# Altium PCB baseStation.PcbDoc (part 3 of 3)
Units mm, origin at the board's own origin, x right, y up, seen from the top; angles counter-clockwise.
Board outline 130 x 90 mm, 4 copper layers (Top Layer, Ground Layer, Power Layer, Bottom Layer), stack 1.574 mm thick; 252 components, 154 nets, 772 pads, 1223 vias.
Unrouted connection lines stored in the file: 134.
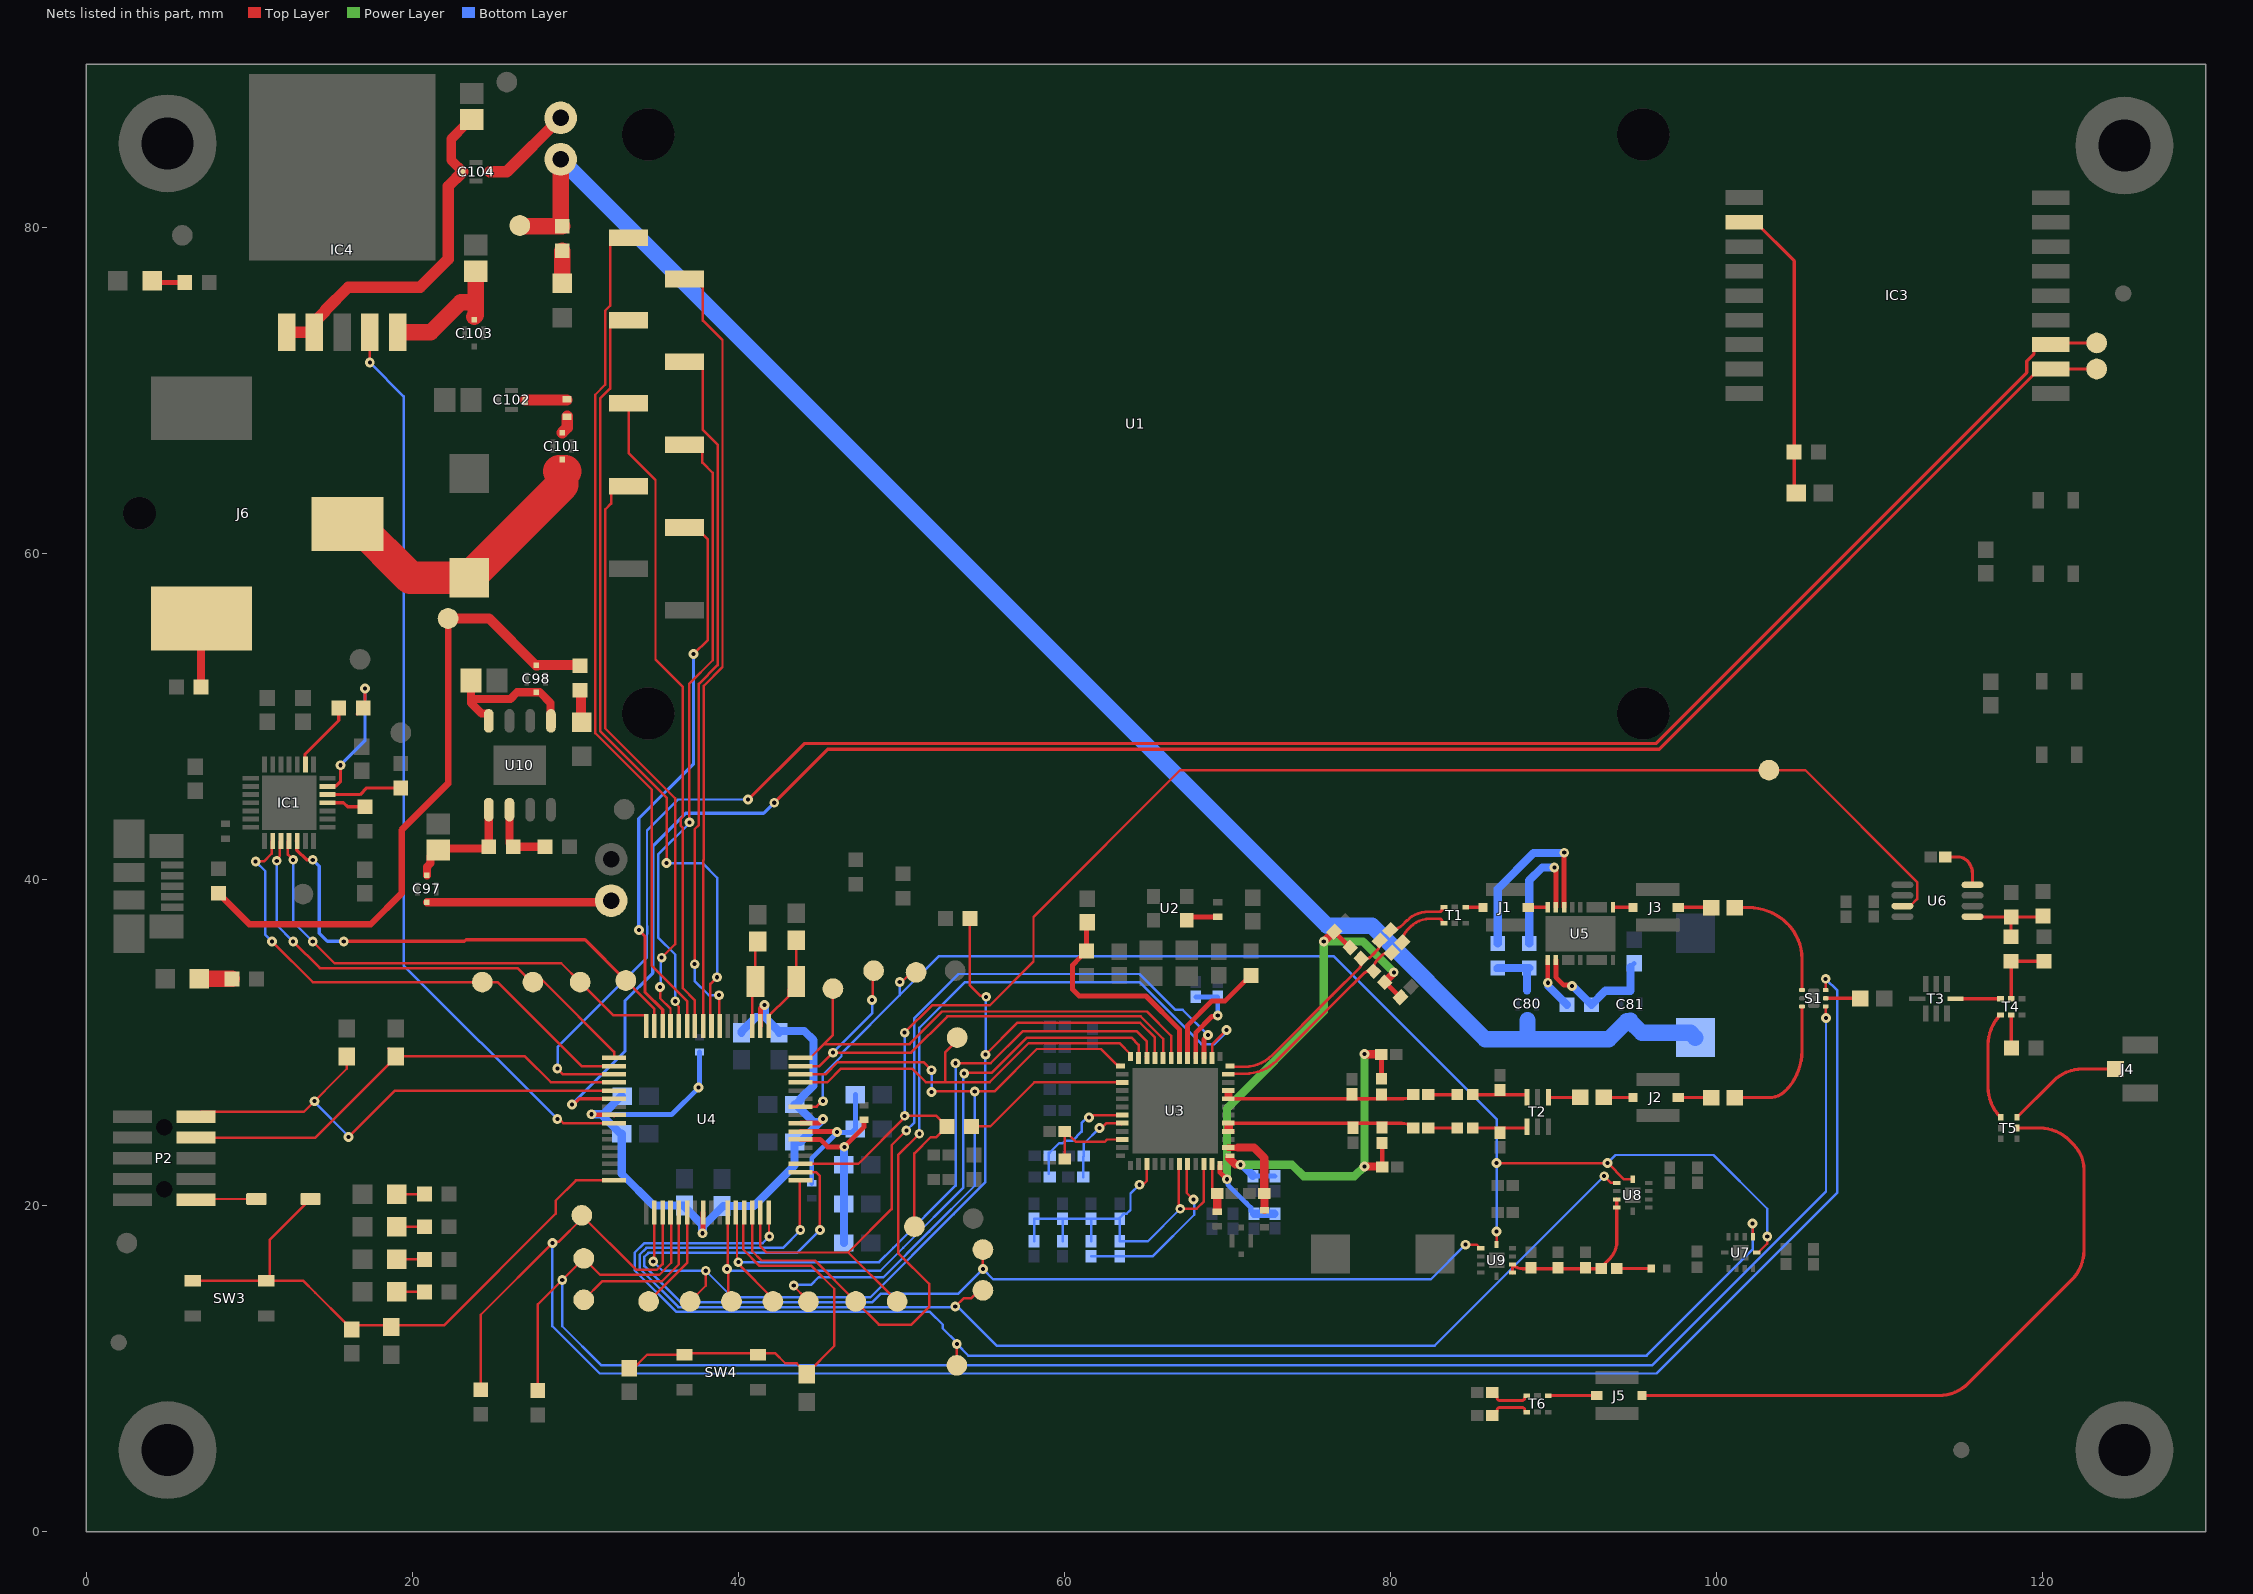
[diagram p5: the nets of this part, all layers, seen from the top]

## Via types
v1: diameter 0.6, hole 0.25, Top Layer to Bottom Layer, tented both sides, 1129 vias
v2: diameter 0.6, hole 0.25, Top Layer to Bottom Layer, 71 vias
v3: diameter 0.66, hole 0.33, Top Layer to Bottom Layer, 17 vias
v4: diameter 0.5, hole 0.2, Top Layer to Bottom Layer, 6 vias

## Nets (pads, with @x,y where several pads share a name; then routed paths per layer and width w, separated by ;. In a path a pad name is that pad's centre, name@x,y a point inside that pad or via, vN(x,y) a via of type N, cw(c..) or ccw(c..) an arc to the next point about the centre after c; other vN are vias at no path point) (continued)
NetC30_2: C30.2 L4.1 | length 1.8
  Top Layer w0.199: C30.2@82.306,26.8 L4.1@84.09,26.8
NetC32_2: C32.2 L4.2 T2.3 | length 3.5
  Top Layer w0.199: L4.2@85.047,26.8 86.71,26.8 88.319,26.8 88.37,26.749 T2.3@88.37,26.64
NetC39_1: C39.1 T2.1 | length 2
  Top Layer w0.199: T2.1@89.68,26.64 ccw(c89.704,26.664) 89.704,26.63 C39.1@91.624,26.63
  Top Layer w0.62: C39.1@91.619,26.635 C39.1@91.624,26.63
NetC39_2: C39.2 J2.IN | length 1.8
  Top Layer w0.199: C39.2@93.076,26.63 J2.IN@94.865,26.63
NetC41_2: C41.2 L6.1 | length 1.8
  Top Layer w0.199: C41.2@82.306,24.76 L6.1@84.09,24.76
NetC51_2: C51.2 L6.2 T2.4 | length 3.4
  Top Layer w0.199: L6.2@85.047,24.76 86.71,24.76 88.319,24.76 88.37,24.81 T2.4@88.37,24.84
NetC59_2: C59.2 C60.2 U3.8 | length 10.7
  Top Layer w0.15: U3.8@67.55,22.55 67.5,22.5 67.5,20.78 v1(67.919,20.361)
  Bottom Layer w0.15: C59.2@61.64,16.894 C60.2@63.39,16.894 65.419,16.894 67.96,19.435 67.96,20.32 v1(67.919,20.361)
NetC62_2: C62.2 C63.2 C64.2 C65.2 C66.2 C67.2 C68.2 C69.2 FB5.2 U4.8 U4.24 U4.34 U4.56 | length 52.5
  Top Layer w0.3: v1(31,25.6) 31.036,25.564 32.375,25.564 U4.56@32.385,25.554 ; v1(37.8,18.3) 37.836,18.336 U4.8@37.836,19.575 ; U4.34@41.351,31.015 41.351,32.086 41.565,32.3 v1(41.6,32.3) ; U4.24@43.825,25.056 44.956,25.056 v1(45.2,25.3)
  Power Layer w0.5: v1(31,25.6) v1@31.019,25.581
  Bottom Layer w0.3: 31.593,25.581 35.912,25.581 v1(37.565,27.234) 37.63,27.298 FB5.2@37.63,29.416
  Bottom Layer w0.5: C62.2@32.874,26.7 32.8,26.7 31.719,25.619 31.019,25.619 v1(31,25.6) 31.019,25.581 31.593,25.581 32.774,24.4 C63.2@32.848,24.4 32.848,21.952 34.8,20 C66.2@36.7,20 36.7,19.926 37.781,18.845 37.781,18.319 v1(37.8,18.3) 37.819,18.319 37.819,18.719 39.074,19.974 40.964,19.974 43.452,22.462 C68.2@43.452,23.9 43.8,23.9 v1@45.019,25.119 ; C64.2@40.2,30.6 40.2,30.674 41.081,31.555 41.619,31.555 ; v1(41.6,32.3) 41.619,32.281 41.619,31.625 41.619,31.555 ; C69.2@43.452,26.2 C69.2@43.526,26.2 ; v1(45.2,25.3) v1@45.019,25.119 ; 41.619,31.555 42.5,30.674 C65.2@42.5,30.6 42.6,30.7 44.04,30.7 44.6,30.14 44.6,27.348 43.805,26.553 43.805,26.479 C69.2@43.526,26.2 ; C69.2@43.526,26.2 44.607,25.119 v1@45.019,25.119
NetC70_2: C70.2 C71.2 FB6.2 U4.23 | length 9.4
  Top Layer w0.3: U4.23@43.815,24.538 46.009,24.538 v1(46.047,24.501)
  Bottom Layer w0.3: FB6.2@44.5,21.354 44.5,22.9 46.047,24.447 v1(46.047,24.501) ; v1@46.024,24.476 46.95,24.476 C70.2@47.174,24.7 C71.2@47.174,26.8
NetC72_2: C72.2 IC3.2 R12.1 | length 18.3
  Top Layer w0.2: IC3.2@101.686,80.3 102.379,80.3 104.749,77.93 R12.1@104.749,66.2 104.749,63.825 C72.2@104.874,63.7
NetC73_2: C73.2 C74.2 C75.2 FB7.1 U4.22 | length 10.9
  Top Layer w0.3: U4.22@43.815,24.055 45.023,24.055 45.478,23.6 v2(46.5,23.6) 47.7,24.8 FB7.1@47.7,25.246
  Bottom Layer w0.5: C73.2@46.474,17.7 C74.2@46.474,20.1 C75.2@46.474,22.5 46.474,23.574 v2(46.5,23.6)
NetC80_3: C80.3 R24.2 R25.2 | length 3.5
  Bottom Layer w0.3: R25.2@86.46,34.459 R25.2@86.57,34.569 R25.2@86.571,34.568 ; R24.2@88.37,34.438 R24.2@88.5,34.568
  Bottom Layer w0.5: R25.2@86.571,34.568 R24.2@88.5,34.568 ; C80.3@88.37,33.185 R24.2@88.37,34.438
NetC81_3: C81.3 C83.2 R23.2 U5.2 | length 8.5
  Top Layer w0.3: U5.2@90.14,35.05 90.14,34 90.623,33.517 91.063,33.517 v1(91.12,33.46)
  Bottom Layer w0.3: v1(91.12,33.46) v1@91.172,33.46 ; C83.2@94.71,34.624 C83.2@94.94,34.854
  Bottom Layer w0.5: v1@91.172,33.46 92.321,32.311 93.185,33.175 C81.3@94.71,33.175 C83.2@94.71,34.624
NetC84_1: C84.1 J2.OUT | length 2
  Top Layer w0.199: J2.OUT@97.64,26.63 ccw(c97.664,26.654) 97.664,26.62 C84.1@99.664,26.62
  Top Layer w0.62: C84.1@99.659,26.625 C84.1@99.664,26.62
NetC84_2: C84.2 S1.6 | length 8.7
  Top Layer w0.199: C84.2@101.116,26.62 102.118,26.62 103.229,26.62 ccw(c103.229,28.01) 104.211,27.026 ccw(c101.753,29.486) 105.23,29.486 S1.6@105.23,32.21
NetC85_1: C85.1 S1.2 | length 2.1
  Top Layer w0.199: S1.2@106.68,32.71 108.79,32.71 cw(c108.79,32.676) C85.1@108.814,32.7
NetC86_1: C86.1 J3.OUT | length 2.1
  Top Layer w0.199: J3.OUT@97.635,38.29 99.616,38.29 cw(c99.616,38.222) 99.651,38.28 cw(c99.616,38.222) C86.1@99.664,38.27
  Top Layer w0.62: C86.1@99.64,38.28 cw(c99.64,38.246) C86.1@99.664,38.27 99.654,38.28 99.651,38.28 C86.1@99.64,38.28
NetC86_2: C86.2 S1.4 | length 7.8
  Top Layer w0.199: C86.2@101.116,38.27 101.968,38.27 cw(c101.968,34.925) 104.332,37.292 cw(c102.168,35.125) 105.23,35.125 105.23,35.124 S1.4@105.23,33.21
NetC89_2: C89.2 U6.4 | length 3
  Top Layer w0.199: C89.2@114.026,41.38 114.781,41.38 cw(c114.781,40.561) 115.36,41.14 cw(c114.563,40.343) 115.69,40.343 U6.4@115.69,39.665
NetC90_1: C90.1 R31.1 | length 2.1
  Top Layer w0.199: R31.1@93.879,16.13 cw(c93.903,16.106) 93.903,16.14 C90.1@95.975,16.14
  Top Layer w0.3: C90.1@95.97,16.13 ccw(c95.97,16.164) C90.1@95.994,16.14
NetC97_1: C97.1 C100.2 R35.2 U10.1 | length 7.4
  Top Layer w0.5: C97.1@20.9,40.247 20.9,40.772 21.122,40.994 21.122,41.397 21.524,41.799 C100.2@21.6,41.799 ; C100.2@21.55,41.799 21.65,41.9 24.597,41.9 R35.2@24.698,42 24.696,42.001 24.696,44.274 U10.1@24.695,44.275
NetC97_3: C97.3 W1.1 | length 11.3
  Top Layer w0.5: C97.3@20.9,38.597 32.097,38.597 W1.1@32.2,38.7
NetC98_3: C98.3 C99.2 U10.5 U10.8 | length 9.6
  Top Layer w0.5: C99.2@23.598,52.2 23.598,51.072 ; U10.8@24.695,49.725 24.695,50.123 24.649,50.169 24.251,50.169 23.598,50.822 23.598,51.072 ; U10.5@28.505,49.725 28.486,49.744 28.486,50.814 27.825,51.475 C98.3@27.6,51.475 26.421,51.475 26.018,51.072 23.598,51.072
NetC101_1: C101.1 C105.1 J6.1 | length 18.3
  Top Layer w2: J6.1@16.025,61.8 16.575,61.8 19.875,58.5 C105.1@23.5,58.5 29.2,64.2 29.2,65.025 29.376,65.025 29.382,65.031 29.018,65.031
NetC101_3: C101.3 FB8.1 | length 1.1
  Top Layer w0.7: C101.3@29.2,67.4 29.5,67.7 FB8.1@29.5,68.396
NetC102_1: C102.1 FB8.2 | length 2.5
  Top Layer w0.7: C102.1@26.925,69.4 FB8.2@29.467,69.4
NetC103_3: C103.3 C107.2 IC4.5 | length 8.4
  Top Layer w1: IC4.5@19.104,73.558 21.137,73.558 22.979,75.4 23.9,75.4 ; 23.8,74.5 23.9,74.6 23.9,75.4 ; C107.2@23.9,77.3 23.9,75.4
NetC104_1: C104.1 C108.2 IC4.1 IC4.2 | length 21.4
  Top Layer w0.6: C104.1@23.1,83.4 22.4,84.1 22.4,85.422 C108.2@23.275,86.297
  Top Layer w0.7: IC4.1@12.296,73.558 IC4.2@13.998,73.558 13.998,74.167 14.666,74.836 14.666,74.908 16.085,76.327 20.497,76.327 22.2,78.03 22.2,82.5 C104.1@23.1,83.4
NetC104_3: C104.3 W2.1 | length 5.7
  Top Layer w0.7: C104.3@24.75,83.4 25.8,83.4 W2.1@29.1,86.7
NetD1_A: D1.A R15.1 | length 1.7
  Top Layer w0.15: D1.A@19.05,20.7 R15.1@20.749,20.7
NetD2_A: D2.A R16.1 | length 1.7
  Top Layer w0.15: D2.A@19.05,18.7 R16.1@20.749,18.7
NetD3_A: D3.A R17.1 | length 1.7
  Top Layer w0.15: D3.A@19.05,16.7 R17.1@20.749,16.7
NetD4_A: D4.A R18.1 | length 1.7
  Top Layer w0.15: D4.A@19.05,14.7 R18.1@20.749,14.7
NetD5_K: D5.K P2.10 | length 3.7
  Top Layer w0.15: P2.10@6.79,20.4 D5.K@10.44,20.4 D5.K@10.5,20.46
NetD6_A: D6.A R34.1 | length 2
  Top Layer w0.6: R34.1@30.3,51.6 30.35,51.55 30.35,49.7 D6.A@30.4,49.65
NetD7_A: D7.A R36.1 | length 2
  Top Layer w1: D7.A@6.95,33.9 R36.1@8.949,33.9
NetD8_A: D8.A R39.1 | length 2
  Top Layer w0.3: D8.A@4.05,76.7 4.15,76.6 R39.1@6.049,76.6
NetD9_A: D9.A R40.1 | length 2
  Top Layer w1: D9.A@29.2,76.55 R40.1@29.2,78.549
NetFB2_2: FB2.2 U2.4 | length 2
  Top Layer w0.3: U2.4@67.5,37.5 67.696,37.696 FB2.2@69.4,37.696
NetIC1_4: IC1.4 R4.2 | length 2.5
  Top Layer w0.2: IC1.4@14.726,44.7 15.785,44.7 16.034,44.451 R4.2@17.1,44.451
NetIC1_5: IC1.5 R3.2 | length 4.7
  Top Layer w0.2: IC1.5@14.726,45.2 16.805,45.2 17.214,45.609 R3.2@19.3,45.609
NetIC1_6: IC1.6 R2.2 | length 9.1
  Top Layer w0.2: IC1.6@14.726,45.7 14.776,45.75 15.354,45.75 15.6,45.996 v2(15.6,47) ; R2.2@16.62,50.144 16.648,50.144 R2.2@17.002,50.499 ; R2.2@17.002,50.5 17.1,50.598 v2(17.1,51.7)
  Bottom Layer w0.2: v2(15.6,47) 17.1,48.5 v2(17.1,51.7)
NetIC1_9: IC1.9 R2.1 | length 4.3
  Top Layer w0.2: IC1.9@13.426,47.1 13.426,47.67 15.5,49.744 R2.1@15.5,50.5
NetIC1_23: IC1.23 TP4.1 U4.50 | length 31.4
  Top Layer w0.15: v2(10.4,41.1) 10.9,41.1 11.376,41.576 IC1.23@11.376,42.35 ; v2(11.4,36.2) 13.9,33.7 TP4.1@24.3,33.7 25.239,33.7 30.388,28.551 U4.50@32.385,28.551
  Bottom Layer w0.15: v2(10.4,41.1) 11,40.5 11,36.6 v2(11.4,36.2)
NetIC1_24: IC1.24 TP3.1 U4.49 | length 29.6
  Top Layer w0.15: v2(11.692,41.139) 11.692,41.26 11.876,41.444 IC1.24@11.876,42.35 ; v2(12.7,36.2) 14.34,34.56 26.452,34.56 27.312,33.7 TP3.1@27.4,33.7 27.5,33.8 28.009,33.8 32.385,29.424 U4.49@32.385,29.059
  Bottom Layer w0.15: v2(11.692,41.139) 11.692,37.208 v2(12.7,36.2)
NetIC1_25: IC1.25 TP2.1 U4.48 | length 29.7
  Top Layer w0.15: IC1.25@12.376,42.35 12.376,41.524 v2(12.7,41.2) ; v2(13.9,36.2) 15.24,34.86 29.14,34.86 TP2.1@30.3,33.7 32.323,31.677 34.276,31.677 34.341,31.612 U4.48@34.341,31.015
  Bottom Layer w0.15: v2(12.7,41.2) 12.7,37.4 v2(13.9,36.2)
NetIC1_26: IC1.26 TP1.1 U4.47 | length 30.1
  Top Layer w0.15: TP1.1@33.1,33.8 34.849,32.051 U4.47@34.849,31.015
  Top Layer w0.2: IC1.26@12.876,42.35 12.926,42.3 12.926,41.796 13.522,41.2 v2(13.9,41.2) ; v2(15.8,36.2) 23.204,36.2 23.304,36.3 30.6,36.3 TP1.1@33.1,33.8
  Bottom Layer w0.2: v2(13.9,41.2) 14.3,40.8 14.3,36.7 14.8,36.2 v2(15.8,36.2)
NetJ1_IN: J1.IN T1.1 | length 1.1
  Top Layer w0.199: T1.1@84.6,38.295 85.65,38.295 J1.IN@85.655,38.29
NetJ1_OUT: J1.OUT U5.13 | length 1.2
  Top Layer w0.199: J1.OUT@88.43,38.29 U5.13@89.64,38.29
NetJ5_IN: J5.IN T5.5 | length 41.6
  Top Layer w0.199: J5.IN@95.405,8.35 113.628,8.35 ccw(c113.628,10.89) 115.424,9.094 121.776,15.446 ccw(c119.98,17.242) 122.52,17.242 122.52,22.209 ccw(c120.369,22.209) 121.89,23.73 121.614,24.006 ccw(c119.818,22.21) 119.818,24.75 T5.5@118.415,24.75
NetJ5_OUT: J5.OUT T6.1 | length 3
  Top Layer w0.199: T6.1@89.67,8.325 cw(c89.73,8.265) 89.73,8.35 J5.OUT@92.63,8.35
NetJ6_3: J6.3 R38.1 | length 4.2
  Top Layer w0.5: R38.1@7.051,51.8 7.051,55.976 J6.3@7.075,56
NetL8_1: L8.1 R31.2 R32.1 R33.1 U8.8 U8.9 U9.1 U9.2 | length 10.6
  Top Layer w0.199: U9.1@87.475,15.881 U9.2@87.475,16.381 ccw(c88.082,16.988) 88.082,16.13 R31.2@92.921,16.13 cw(c93.142,16.13) 92.986,16.286 93.44,16.74 ccw(c92.39,17.79) 93.875,17.79 U8.8@93.875,20.38
NetR11_1: R11.1 TP16.1 TP28.1 U4.19 U6.7 | length 98.1
  Top Layer w0.15: U4.19@43.815,22.557 47.357,22.557 50.2,25.4 v1(50.2,25.5) 52.15,25.5 R11.1@52.799,24.851 ; v1(50.2,30.6) 51.875,32.275 55.417,32.275 58.1,34.958 58.1,37.7 67.1,46.7 TP28.1@103.2,46.7 105.431,46.7 112.29,39.841 112.29,38.79 111.865,38.365 U6.7@111.39,38.365 ; TP16.1@50.8,18.7 50.8,23.2 51.8,24.2 52.15,24.2 R11.1@52.799,24.85
  Bottom Layer w0.15: v1(50.2,25.5) v1(50.2,30.6)
NetR13_2: R13.2 S1.3 TP25.1 U4.3 | length 126.9
  Top Layer w0.15: R13.2@24.2,8.7 24.2,13.3 28.686,17.786 28.996,17.786 30.4,19.19 TP25.1@30.4,19.4 33.75,16.05 35,16.05 35.357,16.407 U4.3@35.357,19.585 ; S1.3@106.68,33.21 v1(106.681,33.904)
  Bottom Layer w0.15: v2(28.6,17.7) 28.6,12.6 31.5,9.7 96.3,9.7 107.4,20.8 107.4,33.184 v1(106.681,33.904)
NetR14_2: R14.2 S1.1 TP24.1 U4.4 | length 115.6
  Top Layer w0.15: R14.2@27.7,8.651 27.7,13.94 v2(29.2,15.44) TP24.1@30.52,16.76 31.53,15.75 35.15,15.75 35.888,16.488 35.888,19.537 U4.4@35.839,19.585 ; S1.1@106.68,32.21 106.69,32.2 106.69,31.51 v1(106.7,31.5)
  Bottom Layer w0.15: v2(29.2,15.44) 29.2,12.6 31.6,10.2 96.038,10.2 106.7,20.862 v1(106.7,31.5)
NetR23_1: R23.1 U5.1 | length 3.2
  Top Layer w0.3: v1(89.64,33.66) U5.1@89.64,35.05
  Bottom Layer w0.3: v1(89.64,33.66) 89.697,33.603 v1@89.697,33.433
  Bottom Layer w0.5: v1@89.697,33.433 R23.1@90.819,32.311
NetR24_1: R24.1 U5.12 | length 8.2
  Top Layer w0.3: v1(90.04,40.73) 90.04,40.649 90.14,40.549 U5.12@90.14,38.29
  Bottom Layer w0.5: R24.1@88.5,36.07 88.5,39.93 89.3,40.73 v1(90.04,40.73)
NetR25_1: R25.1 U5.11 | length 11.7
  Top Layer w0.3: U5.11@90.64,38.29 90.645,38.295 90.645,41.635 v1(90.65,41.64)
  Bottom Layer w0.3: v1@90.62,41.61 v1(90.65,41.64)
  Bottom Layer w0.5: R25.1@86.57,36.071 86.57,39.41 88.77,41.61 v1@90.62,41.61
NetR26_1: R26.1 R28.1 T4.5 | length 4.3
  Top Layer w0.199: T4.5@118.06,32.675 118.06,34.955 ccw(c118.026,34.955) R26.1@118.05,34.979 R28.1@120.06,34.979
NetR26_2: R26.2 R27.1 R30.1 U6.1 | length 5.7
  Top Layer w0.199: U6.1@115.69,37.715 ccw(c115.753,37.778) 115.753,37.689 R27.1@118.06,37.689 R27.1@118.075,37.689 ; R26.2@118.05,36.481 118.05,37.616 cw(c118.167,37.616) R27.1@118.075,37.689 ; R27.1@118.084,37.699 ccw(c118.167,37.616) R27.1@118.075,37.689 ; R30.1@120,37.749 cw(c119.855,37.894) 119.855,37.689 R27.1@118.075,37.689
  Top Layer w0.62: R27.1@118.047,37.702 R27.1@118.06,37.689 ; R26.2@118.05,36.481 R26.2@118.055,36.486 ; R27.1@118.05,37.665 cw(c118.084,37.665) R27.1@118.055,37.682 ; R27.1@118.104,37.719 118.084,37.699 ccw(c118.084,37.665) R27.1@118.06,37.689 ; R30.1@119.97,37.719 R30.1@120,37.749 ; R27.1@118.055,37.682 cw(c118.084,37.665) R27.1@118.06,37.689 ; R27.1@118.055,37.682 118.055,37.684 R27.1@118.06,37.689
NetR29_1: R29.1 T4.2 | length 2
  Top Layer w0.199: T4.2@118.06,31.685 118.06,29.715 ccw(c118.124,29.715) R29.1@118.079,29.67
NetR35_1: R35.1 R37.2 U10.2 | length 4
  Top Layer w0.5: R35.1@25.965,42.236 U10.2@25.965,44.275 ; R35.1@26.2,42 R37.2@28.149,42
NetT3_4: T3.4 T4.6 | length 2.8
  Top Layer w0.199: T3.4@114.645,32.68 117.395,32.68 T4.6@117.4,32.675
NetTP29_1: TP29.1 U4.16 U7.6 | length 88.6
  Top Layer w0.15: U4.16@41.859,19.585 41.88,19.565 41.88,18.12 v1(41.9,18.1) ; TP29.1@53.4,10.2 53.4,11.328 53.486,11.414 v2(53.4,11.5) ; v1(102.2,18.9) 102.21,18.89 102.21,18.095 U7.6@102.22,18.085
  Bottom Layer w0.15: v1(41.9,18.1) 41.5,17.7 34.236,17.7 33.642,17.106 33.642,16.033 36.201,13.475 51.755,13.475 52.534,12.696 52.534,12.466 53.4,11.6 v2(53.4,11.5) 54.1,10.8 95.7,10.8 102.2,17.3 v1(102.2,18.9)
NetTP30_1: TP30.1 U4.18 U9.6 | length 72.1
  Top Layer w0.15: U4.18@43.815,22.049 44.751,22.049 45,21.8 v1(45,18.5) ; v2(55,16.1) TP30.1@55,17.3 ; v1(84.6,17.6) 85.287,17.6 85.375,17.512 85.375,17.431 85.425,17.381 U9.6@85.525,17.381
  Bottom Layer w0.15: v1(45,18.5) 43.6,17.1 34.485,17.1 34.242,16.858 34.242,16.282 36.449,14.075 48.224,14.075 48.749,14.6 53.5,14.6 v2(55,16.1) 55.623,15.477 82.477,15.477 v1(84.6,17.6)
NetTP31_1: TP31.1 U4.17 U8.6 | length 82.9
  Top Layer w0.15: v1@43.76,18.5 43.76,21.486 U4.17@43.815,21.541 ; v2(53.3,13.8) 53.808,14.308 54.276,14.308 54.768,14.8 TP31.1@55,14.8 ; v1(93.1,21.8) 93.513,21.387 93.868,21.387 U8.6@93.875,21.38
  Bottom Layer w0.15: v1(43.8,18.5) 43.8,18.457 42.743,17.4 34.5,17.4 34.361,17.4 33.942,16.982 33.942,16.158 36.325,13.775 53.275,13.775 v2(53.3,13.8) 53.325,13.775 53.475,13.775 55.842,11.408 57.532,11.408 57.54,11.4 82.7,11.4 v1(93.1,21.8)
NetU1_3: U1.3 U4.46 | length 33.9
  Top Layer w0.15: U1.3@36.7,61.58 37.395,61.58 38.13,60.845 38.13,54.69 v2(37.255,53.815)
  Top Layer w0.2: v2(33.9,36.9) 34.275,36.525 34.275,33.085 35.357,32.003 U4.46@35.357,31.015
  Bottom Layer w0.2: v2(33.9,36.9) 33.9,43.734 37.255,47.089 v2(37.255,53.815)
NetU1_4: U1.4 U4.45 | length 35.7
  Top Layer w0.15: U1.4@32.2,64.108 32.2,63.05 31.84,62.69 31.84,49.26 36.125,44.975 36.125,36.025 v2(35.3,35.2) ; v2(35.2,33.4) 35.2,32.715 35.839,32.076 U4.45@35.839,31.015
  Bottom Layer w0.15: v2(35.2,33.4) 35.25,33.45 35.25,35.15 v2(35.3,35.2)
NetU1_5: U1.5 U4.44 | length 37.5
  Top Layer w0.15: v2(36.129,32.529) 36.129,32.407 36.347,32.188 U4.44@36.347,31.015 ; v2(37,43.5) 37,52.013 38.43,53.443 38.43,64.93 37.8,65.56 U1.5@37.8,66.3
  Bottom Layer w0.15: v2(36.129,32.529) 36.129,35.389 35.075,36.443 35.075,38.541 35.075,41.517 37,43.442 v2(37,43.5)
NetU1_6: U1.6 U4.42 | length 40
  Top Layer w0.15: U1.6@33.27,69.2 33.27,66.153 34.92,64.503 34.92,53.48 36.6,51.8 36.6,43.842 36.475,43.717 36.475,43.283 36.6,43.158 36.6,33.321 37.338,32.583 U4.42@37.338,31.015
NetU1_7: U1.7 U4.39 | length 43.6
  Top Layer w0.15: U1.7@36.7,71.74 37.395,71.74 37.83,71.305 37.83,67.563 38.73,66.663 38.73,53.144 37.577,51.991 37.577,43.335 37.321,43.079 v2(37.321,34.8) ; v2(38.814,32.9) 38.838,32.876 38.838,31.039 U4.39@38.862,31.015
  Bottom Layer w0.15: v2(37.321,34.8) 37.321,33.762 38.183,32.9 v2(38.814,32.9)
NetU1_8: U1.8 U4.40 | length 48.9
  Top Layer w0.15: U1.8@33.27,74.28 32.575,74.28 32.14,73.845 32.14,70.103 31.525,69.488 31.525,49.099 35.6,45.024 v2(35.6,41) ; U4.40@38.354,31.015 38.289,31.079 38.289,33.59 v2(38.7,34)
  Bottom Layer w0.15: v2(35.6,41) 37.8,41 38.7,40.1 v2(38.7,34)
NetU1_9: U1.9 U4.41 | length 47.7
  Top Layer w0.15: U1.9@36.7,76.82 37.395,76.82 37.83,76.385 37.83,74.27 39.03,73.07 39.03,53.02 37.877,51.867 37.877,41.211 37.846,41.179 U4.41@37.846,31.015
NetU1_10: U1.10 U4.43 | length 51.9
  Top Layer w0.15: U1.10@33.27,79.36 32.575,79.36 32.14,78.925 32.14,75.183 31.84,74.883 31.84,70.34 31.225,69.725 31.225,48.975 34.7,45.5 34.7,34.7 36.855,32.545 U4.43@36.855,31.015
nRESET: C78.2 D5.A R21.1 SW3.1 SW3.2 U4.64 | length 37.2
  Top Layer w0.15: SW3.1@6.55,15.375 SW3.2@11.275,15.375 ; D5.A@13.76,20.4 11.275,17.915 SW3.2@11.275,15.375 ; C78.2@16.3,12.4 16.3,12.424 15.896,12.828 15.872,12.828 14.052,14.648 13.325,15.375 SW3.2@11.275,15.375 ; C78.2@16.4,12.65 21.95,12.65 28.8,19.5 28.8,20.3 30.041,21.541 U4.64@32.385,21.541 ; R21.1@18.7,12.551 R21.1@18.7,12.6
OSCI: R9.1 U3.29 | length 7.2
  Top Layer w0.3: U3.29@67.55,29.05 67.55,31.05 69.05,32.55 69.85,32.55 71.094,33.794 71.145,33.794 R9.1@71.45,34.099
OSCO: C8.2 R8.2 U3.30 | length 13.8
  Top Layer w0.15: R8.2@60.969,35.221 R8.2@61.349,35.601
  Top Layer w0.3: R8.2@60.969,35.221 60.5,34.752 60.5,33.25 60.9,32.85 65,32.85 67.05,30.8 U3.30@67.05,29.05 ; R8.2@61.35,35.601 61.35,37.324 C8.2@61.4,37.374
PA_OUT: J3.IN U5.7 | length 1.2
  Top Layer w0.199: U5.7@93.64,38.29 J3.IN@94.86,38.29
PAOUT_N: C41.1 C50.1 L5.2 U3.16 U3.17 | length 11.9
  Top Layer w0.199: U3.17@70.05,25.05 80.694,25.05 cw(c80.694,24.06) C41.1@81.394,24.76
  Top Layer w0.3: U3.16@70.05,24.55 U3.16@70.275,24.55
  Top Layer w0.5: 70.07,24.715 U3.17@70.07,24.925
PAOUT_P: C30.1 C31.1 L3.2 U3.20 U3.21 | length 11.6
  Top Layer w0.199: U3.20@70.05,26.55 77.64,26.55 79.43,26.55 80.791,26.55 ccw(c80.791,27.404) C30.1@81.394,26.8
  Top Layer w0.5: 70.05,26.7 U3.21@70.05,26.91
PIO0_31: C79.2 R22.1 SW4.1 SW4.2 U4.13 | length 26.8
  Top Layer w0.15: C79.2@33.3,10.026 33.438,9.888 34.4,10.85 SW4.1@36.7,10.85 ; SW4.1@36.7,10.95 41.2,10.95 42.25,10.95 42.875,10.325 43.575,10.325 R22.1@44.2,9.7 ; U4.13@40.361,19.585 40.3,19.524 40.3,17.306 41.306,16.3 44.485,16.3 45.885,14.9 45.885,11.385 R22.1@44.2,9.7 ; R22.1@44.2,9.7 R22.1@44.2,9.651 R22.1@44.2,9.7
rfid_reader_ADC: R11.2 U3.39 | length 10.4
  Top Layer w0.15: R11.2@54.301,24.85 55.45,24.85 58.15,27.55 U3.39@63.55,27.55
rfid_reader_CLSYS: TP15.1 U3.36 U4.29 | length 25.4
  Top Layer w0.15: U4.29@43.815,27.561 45.461,27.561 46.3,28.4 50.661,28.4 51.5,27.561 52.7,27.561 ; TP15.1@53.42,30.3 53.42,30.132 52.7,29.412 52.7,27.561 ; U3.36@64.05,29.15 64.05,29.275 63.365,29.96 57.81,29.96 55.411,27.561 52.7,27.561
rfid_reader_EN: TP10.1 U3.31 U4.32 | length 30.6
  Top Layer w0.15: U4.32@43.815,29.059 44.412,29.059 45.253,29.9 ; 45.8,32.2 TP10.1@45.8,33.3 45.8,30.447 45.253,29.9 ; U3.31@66.55,29.05 66.55,30.4 65.05,31.9 52.5,31.9 50.5,29.9 45.253,29.9
rfid_reader_IRQ: TP14.1 U3.32 U4.31 | length 31.3
  Top Layer w0.15: U4.31@43.815,28.551 44.976,28.551 v1(45.8,29.375) 50.599,29.375 52.824,31.6 64.674,31.6 66.05,30.224 U3.32@66.05,29.05 ; v1(48.2,32.6) 48.25,32.65 48.25,34.35 TP14.1@48.3,34.4
  Bottom Layer w0.15: v1(45.8,29.375) 48.225,31.8 48.225,32.575 v1(48.2,32.6)
rfid_reader_MISO: TP13.1 U3.34 U4.12 | length 43
  Top Layer w0.15: U4.12@39.853,19.585 39.917,19.52 39.917,16.608 v1(40,16.525) 40,16.403 42.12,14.283 TP13.1@42.12,14.12 ; v1(53.325,28.725) 55.475,28.725 57.45,30.7 64.411,30.7 65.05,30.061 U3.34@65.05,29.125 ; U3.34@64.975,29.125 U3.34@65.05,29.05
  Bottom Layer w0.15: v1(40,16.525) 40.01,16.535 48.635,16.535 49.5,17.4 53.325,21.225 v1(53.325,28.725)
rfid_reader_MOSI: TP12.1 U3.35 U4.11 | length 41.4
  Top Layer w0.15: v1(39.3,16.1) 39.386,16.014 39.386,14.314 TP12.1@39.58,14.12 ; U4.11@39.345,19.585 39.348,19.581 39.348,16.333 v1@39.352,16.33 ; v1@54.1,28.15 55.55,28.15 57.7,30.3 64.1,30.3 64.55,29.85 U3.35@64.55,29.05
  Bottom Layer w0.15: v1(39.3,16.1) 39.386,16.014 39.769,16.014 39.783,16 48.7,16 50.112,17.412 53.8,21.1 53.8,28.05 v1(53.85,28.1)
rfid_reader_nCS: R10.2 TP9.1 U3.33 U4.2 | length 58.8
  Top Layer w0.15: v1@34.849,16.838 U4.2@34.849,19.585 ; TP9.1@37.04,14.12 38,15.08 v1(38,16) ; R10.2@54.2,37.6 54.2,33.5 54.829,32.871 55.129,32.871 v2(55.2,32.8) ; v1(55.15,29.25) 57.1,31.2 64.65,31.2 65.55,30.3 U3.33@65.55,29.05
  Bottom Layer w0.15: v1(34.783,16.575) 35.358,16 v1(38,16) 39.625,14.375 48.099,14.375 53.2,19.476 53.2,19.486 55.15,21.436 v1(55.15,29.25) 55.175,29.275 55.175,32.775 v2(55.2,32.8)
rfid_reader_OAD: TP17.1 U3.27 U4.15 | length 49.7
  Top Layer w0.15: U4.15@41.351,19.585 41.351,17.499 41.73,17.12 46.74,17.12 ; TP17.1@49.48,14.38 46.74,17.12 ; v1(50.3,24.6) 49.4,23.7 49.4,19.78 46.74,17.12
  Top Layer w0.3: U3.27@68.55,29.05 68.55,30.2 v1(68.8,30.45)
  Bottom Layer w0.15: v1(50.3,24.6) 50.8,25.1 50.8,31.5 53.5,34.2 64.6,34.2 66.8,32 67.25,32 v1(68.8,30.45)
rfid_reader_OAD2: TP18.1 U3.26 U4.14 | length 58.1
  Top Layer w0.15: U4.14@40.843,19.585 40.85,19.578 40.85,17.2 41.42,16.63 44.69,16.63 TP18.1@47.2,14.12 48.62,12.7 50.612,12.7 51.7,13.788 51.7,15.2 49.8,17.1 49.8,23.1 v1(51.1,24.4) ; U3.26@69.05,29.05 69.05,29.881 v1(69.938,30.769)
  Bottom Layer w0.15: v1(51.1,24.4) 51.1,30.9 53.9,33.7 64.6,33.7 68.4,29.9 69.2,29.9 69.938,30.638 v1(69.938,30.769)
rfid_reader_SCK: TP11.1 U3.37 U4.30 | length 43.7
  Top Layer w0.15: v1(43.4,15.1) 43.4,15.05 44.15,14.3 TP11.1@44.3,14.3 ; U4.30@43.815,28.043 45.343,28.043 46.1,28.8 51.35,28.8 v1(51.85,28.3) ; v1(51.851,26.971) 51.88,27 v1(54.5,27) 55.7,27 58.3,29.6 62.25,29.6 63.225,28.625 63.375,28.625 U3.37@63.45,28.55
  Bottom Layer w0.15: v1(43.4,15.1) 43.437,15.137 44.463,15.137 44.925,15.6 48.9,15.6 51.7,18.4 51.7,18.41 54.5,21.21 v1(54.5,27) ; v1@51.85,26.971 v1@51.85,28.3
RFO_N: C22.1 L2.2 U3.23 | length 13.2
  Top Layer w0.175: U3.23@70.136,28.085 71.064,28.085 ccw(c71.064,30.855) 73.023,28.897 76.843,32.717 ; 76.843,32.717 78.35,34.223 cw(c78.736,33.837) L2.2@78.736,34.384 ; L2.2@78.962,34.368 cw(c78.998,34.405) 78.946,34.405 78.946,34.522 cw(c79.657,34.522) 79.154,35.024 79.363,35.232 79.363,35.237 79.442,35.317 cw(c79.828,34.931) C22.1@79.828,35.476
  Top Layer w0.228: U3.23@70.05,28.05 cw(c70.131,27.969) U3.23@70.131,28.083
  Top Layer w0.299: L2.2@78.736,34.384 78.925,34.384 cw(c78.925,34.332) L2.2@78.962,34.368 ; C22.1@79.828,35.476 79.992,35.476 ccw(c79.992,35.584) C22.1@80.068,35.508
RFO_P: C20.1 L1.2 U3.24 | length 12.6
  Top Layer w0.175: U3.24@70.15,28.55 ccw(c70.236,28.636) 70.236,28.514 71.062,28.514 ccw(c71.062,30.86) 72.721,29.202 76.414,32.895 78.056,34.537 ccw(c77.677,34.916) L1.2@78.214,34.916 ; L1.2@78.198,35.142 ccw(c78.235,35.178) 78.235,35.126 78.45,35.126 ccw(c78.45,35.61) 78.792,35.268 78.934,35.41 78.934,35.415 79.203,35.685 ccw(c78.949,35.939) C20.1@79.309,35.939
  Top Layer w0.299: L1.2@78.198,35.142 cw(c78.162,35.105) 78.214,35.105 L1.2@78.214,34.916 ; C20.1@79.309,35.939 cw(c79.477,35.939) C20.1@79.358,36.058
RTCXIN: C76.2 U4.33 Y1.1 | length 6
  Top Layer w0.15: U4.33@41.859,31.015 41.859,31.612 43.075,32.828 43.075,33.26 Y1.1@43.55,33.735 43.55,36.268 C76.2@43.544,36.274
RTCXOUT: C77.1 U4.35 Y1.2 | length 5.3
  Top Layer w0.15: U4.35@40.843,31.015 40.843,33.528 Y1.2@41.05,33.735 41.05,36.053 C77.1@41.185,36.189
RX_ESP32: IC3.11 TP20.1 U4.54 | length 121.3
  Top Layer w0.2: v2(29.8,26.2) 29.908,26.2 30.253,26.545 U4.54@32.385,26.545 ; v2(42.2,44.7) 45.481,47.981 96.47,47.981 119.789,71.3 IC3.11@120.482,71.3 TP20.1@123.3,71.3
  Bottom Layer w0.2: v2(29.8,26.2) 33.05,29.45 33.05,32.555 34.75,34.255 34.75,38.14 34.75,42.028 36.772,44.05 41.55,44.05 v2(42.2,44.7)
RX_N: C61.2 T6.3 | length 2.5
  Top Layer w0.175: C61.2@86.236,8.53 cw(c86.236,8.423) 86.311,8.499 86.481,8.329 cw(c86.367,8.214) 86.529,8.214 ccw(c86.691,8.214) 86.576,8.1 86.58,8.096 ccw(c86.704,8.22) 86.704,8.045 88.057,8.045 ccw(c88.057,8.22) 88.181,8.096 ccw(c88.057,8.22) 88.232,8.22 88.232,8.244 cw(c88.314,8.244) 88.256,8.301 cw(c88.314,8.244) 88.314,8.325 T6.3@88.35,8.325
RX_P: C52.2 T6.4 | length 2.5
  Top Layer w0.175: C52.2@86.296,7.154 86.304,7.154 86.481,7.331 ccw(c86.367,7.446) 86.529,7.446 cw(c86.691,7.446) 86.576,7.56 86.58,7.564 cw(c86.704,7.44) 86.704,7.615 88.057,7.615 cw(c88.057,7.44) 88.181,7.564 cw(c88.057,7.44) 88.232,7.44 88.232,7.416 ccw(c88.314,7.416) 88.256,7.359 ccw(c88.314,7.416) 88.314,7.335 T6.4@88.35,7.335
  Top Layer w0.3: C52.2@86.286,7.13 ccw(c86.261,7.154) C52.2@86.296,7.154
SCK: TP26.1 U4.26 U7.5 U8.5 U9.5 | length 84.7
  Top Layer w0.15: U4.26@43.88,25.997 U4.26@43.815,26.062 44.795,26.062 45.133,26.4 v1(45.2,26.4) ; v2(49.9,33.7) 50.022,33.7 50.622,34.3 TP26.1@50.9,34.3 ; U9.5@86.5,17.606 v1(86.5,18.4) ; v1@86.558,22.6 v1(93.3,22.6) 93.323,22.6 94.318,21.605 U8.5@94.85,21.605 ; U7.5@102.445,17.11 102.545,17.11 103.1,17.665 v1(103.1,18.1)
  Bottom Layer w0.15: v1(45.2,26.4) 45.175,26.425 45.175,28.008 46.325,29.158 46.325,29.325 49.9,32.9 ; v2(49.9,33.7) 49.9,32.9 ; v1(86.5,18.4) v1(86.5,22.6) 86.5,25.3 76.5,35.3 52.3,35.3 49.9,32.9 ; v1(93.3,22.6) 93.8,23.1 99.8,23.1 103.1,19.8 v1(103.1,18.1)
SWCLK/PIO0_16: P2.4 R20.1 U4.52 | length 29.1
  Top Layer w0.15: P2.4@6.75,24.17 14.07,24.17 19,29.1 R20.1@19,29.149 ; R20.1@18.52,29.629 18.569,29.629 19,29.198 R20.1@19,29.149 ; U4.52@32.385,27.561 28.5,27.561 26.912,29.149 R20.1@19,29.149
SWDIO/PIO0_17: P2.2 R19.1 U4.53 | length 31.8
  Top Layer w0.15: P2.2@6.75,25.44 7.055,25.745 13.345,25.745 15.986,28.386 15.986,29.134 R19.1@16,29.149 ; v1(16.1,24.2) 18.953,27.053 U4.53@32.385,27.053
  Bottom Layer w0.15: v1(14,26.4) 14,26.35 16.1,24.25 v1(16.1,24.2)
TX: T4.1 T5.1 | length 6.7
  Top Layer w0.199: T4.1@117.4,31.685 117.384,31.669 ccw(c119.18,29.873) 116.64,29.873 116.64,27.247 ccw(c119.18,27.247) 117.384,25.451 T5.1@117.425,25.41
TX_ESP32: IC3.12 TP19.1 U4.51 | length 122.4
  Top Layer w0.15: v1(28.9,28.4) 29.257,28.043 U4.51@32.385,28.043
  Top Layer w0.2: v2(40.6,44.9) 44.031,48.331 96.262,48.331 107.749,59.818 119.014,71.082 119.014,71.778 119.45,72.215 119.45,72.45 119.8,72.8 IC3.12@120.482,72.8 120.582,72.9 TP19.1@123.3,72.9
  Bottom Layer w0.15: v1(28.9,28.4) 28.921,28.421 28.921,29.721 34.4,35.2 34.4,36.658 34.425,36.683 34.425,37.117 34.4,37.142 34.4,43 36.3,44.9 v2(40.6,44.9)
TX_N: C22.2 T1.4 | length 3.5
  Top Layer w0.175: C22.2@80.744,36.228 cw(c81.671,36.228) 81.015,36.884 81.23,37.099 cw(c82.405,35.924) 82.405,37.586 82.987,37.586 cw(c82.987,37.41) 83.111,37.534 cw(c82.987,37.41) 83.162,37.41 83.162,37.386 ccw(c83.244,37.386) 83.186,37.329 ccw(c83.244,37.386) 83.244,37.305 T1.4@83.28,37.305
  Top Layer w0.299: C22.2@80.712,36.152 ccw(c80.636,36.228) C22.2@80.744,36.228
TX_P: C20.2 T1.3 | length 3.8
  Top Layer w0.175: C20.2@80.06,36.926 ccw(c80.06,37.868) 80.726,37.202 80.995,37.47 cw(c82.309,36.156) 82.309,38.015 82.987,38.015 ccw(c82.987,38.19) 83.111,38.066 ccw(c82.987,38.19) 83.162,38.19 83.162,38.214 cw(c83.244,38.214) 83.186,38.271 cw(c83.244,38.214) 83.244,38.295 T1.3@83.28,38.295
  Top Layer w0.299: C20.2@79.984,36.894 cw(c80.06,36.819) C20.2@80.06,36.926
TX_RX: J4.1 T5.6 | length 7.1
  Top Layer w0.199: T5.6@118.415,25.41 120.631,27.626 cw(c122.427,25.83) 122.427,28.37 J4.1@124.445,28.37
USB_DM: TP22.1 U4.6 | length 6.4
  Top Layer w0.15: TP22.1@34.5,14.12 36.855,16.475 U4.6@36.855,19.585
USB_DP: TP21.1 U4.5 | length 9.9
  Top Layer w0.15: TP21.1@30.52,14.22 31.645,15.345 35.301,15.345 36.347,16.392 U4.5@36.347,19.585
VBUS: C98.1 R1.2 R34.2 TP33.1 | length 40.2
  Top Layer w0.4: R1.2@8.115,39.149 10.015,37.25 17.457,37.25 19.35,39.143 19.35,43.026 22.2,45.876 TP33.1@22.2,56
  Top Layer w0.6: TP33.1@22.2,56 24.725,56 C98.1@27.6,53.125 27.689,53.125 27.714,53.15 30.252,53.15 R34.2@30.3,53.102
VDD_A: C35.1 C36.1 U3.44 | length 5.3
  Top Layer w0.15: v1(62.15,24.75) 62.272,24.75 62.572,25.05 U3.44@63.55,25.05 ; U3.44@63.486,24.986 U3.44@63.55,25.05 ; U3.44@63.55,25.05 63.486,25.05 U3.44@63.55,25.05
  Bottom Layer w0.15: C35.1@61.156,21.74 61.156,23 C36.1@61.186,23.03 61.186,23.786 v1(62.15,24.75) v1@62.028,24.75
VDD_B: C19.1 C21.1 C46.1 C47.1 L1.1 L2.1 U3.12 | length 31.8
  Top Layer w0.3: U3.12@69.55,22.45 69.55,22.019 v1(69.959,21.61) ; C19.1@76.548,36.788 76.55,36.788 77.519,35.818 L1.1@77.522,35.818 ; L2.1@79.638,33.692 79.661,33.692 80.585,32.768 C21.1@80.608,32.768
  Top Layer w0.5: v1(75.9,36.2) 75.927,36.2 76.515,36.788 C19.1@76.548,36.788 ; L2.1@79.638,33.692 79.638,33.715 80.2,34.277 v1(80.2,34.3)
  Power Layer w0.5: v1(69.959,21.61) 69.959,25.949 75.9,31.89 v1(75.9,36.2) 78.3,36.2 v1(80.2,34.3)
  Bottom Layer w0.3: v1@69.959,21.668 v1(69.959,21.61) 70.017,21.553 70.017,21.286 71.152,20.151 71.434,19.869 71.434,19.672 C47.1@71.62,19.486 C47.1@71.63,19.496 ; C46.1@72.89,19.496 C46.1@72.9,19.506
  Bottom Layer w0.5: C47.1@71.63,19.496 C46.1@72.89,19.496
VDD_D: C44.1 C45.1 U3.28 | length 5.8
  Top Layer w0.3: U3.28@68.05,29.05 68.05,30.6 69.043,31.593 69.343,31.593 v1(69.4,31.65)
  Bottom Layer w0.3: C45.1@68.05,32.794 C44.1@69.4,32.794 v1(69.4,31.65)
VDD_LFI: C53.2 C54.2 C55.2 C56.2 C57.1 C58.1 C59.1 C60.1 U3.3 U3.7 U3.10 | length 26.5
  Top Layer w0.15: v1(64.596,21.274) 64.638,21.232 64.762,21.232 65.05,21.52 U3.3@65.05,22.55 ; U3.7@67.05,22.55 67,22.5 67,20.056 67.014,20.042 67.014,20.008 67.222,19.8 v1@67.256,19.8 ; v1(67.1,19.8) v1@67.256,19.8 ; U3.10@68.55,22.55 68.55,20.25 68.1,19.8 v1@67.256,19.8
  Bottom Layer w0.15: C57.1@58.14,17.806 C53.2@58.14,19.189 58.146,19.194 C54.2@59.89,19.194 ; C58.1@59.89,17.806 C54.2@59.89,19.194 ; C59.1@61.64,17.806 C55.2@61.64,19.194 ; v1(64.596,21.274) 64.05,20.728 64.05,19.731 63.819,19.5 63.651,19.5 63.39,19.239 C56.2@63.39,19.194 ; v1(67.1,19.8) 65.106,17.806 C60.1@63.39,17.806 C56.2@63.39,19.194 ; C54.2@59.89,19.194 C55.2@61.64,19.194 ; C55.2@61.64,19.194 C56.2@63.39,19.194
VDD_PA: C23.1 C40.1 C42.1 C43.1 L3.1 L5.1 U3.13 | length 23.4
  Top Layer w0.15: U3.13@70.15,23.05 U3.13@70.275,23.05
  Top Layer w0.3: L3.1@79.43,27.86 79.432,27.862 79.432,29.258 C40.1@79.434,29.26 ; L5.1@79.48,23.738 79.487,23.731 79.487,22.377 C23.1@79.494,22.37
  Top Layer w0.5: U3.13@70.1,22.95 70.1,22.9 70.481,22.519 70.781,22.519 v1(70.8,22.5) ; v1(78.4,22.4) 78.415,22.385 79.479,22.385 C23.1@79.487,22.377 ; v1(78.4,29.3) 78.419,29.281 79.409,29.281 C40.1@79.432,29.258
  Power Layer w0.5: v1(70.8,22.5) 73.959,22.5 74.659,21.8 77.79,21.8 78.39,22.4 v1(78.4,22.4) v1@78.4,29.273
  Bottom Layer w0.3: C43.1@71.55,21.806 71.555,21.801 72.895,21.801 C42.1@72.9,21.796
  Bottom Layer w0.5: v1(70.8,22.5) 70.819,22.481 70.919,22.481 71.55,21.85 C43.1@71.55,21.806
VDDLF: C37.1 C38.1 U3.46 | length 5.6
  Top Layer w0.15: C37.1@60.006,22.85 C38.1@60.006,24.55 60.05,24.55 60.7,23.9 62.467,23.9 62.617,24.05 U3.46@63.55,24.05
VEXT: C16.1 FB4.2 U3.11 | length 3
  Top Layer w0.15: U3.11@69.05,22.55 69.05,21.004 69.314,20.74 C16.1@69.359,20.74 C16.1@69.37,20.729
  Top Layer w0.5: FB4.2@69.37,19.687 C16.1@69.37,20.729
VEXT_PA: C17.1 FB3.2 U3.14 | length 5.7
  Top Layer w0.15: C17.1@72.256,20.73 C17.1@72.26,20.726
  Top Layer w0.4: U3.14@70.05,23.55 70.57,23.55 70.575,23.555 70.645,23.555
  Top Layer w0.5: 70.65,23.55 71.625,23.55 72.256,22.919 C17.1@72.256,20.73 ; FB3.2@72.26,19.723 C17.1@72.26,20.726
VOSC: C33.1 C34.1 U3.43 | length 7.1
  Top Layer w0.15: v1(61.5,25.4) 61.622,25.4 61.747,25.525 63.525,25.525 U3.43@63.55,25.55
  Bottom Layer w0.15: C33.1@59.041,21.939 59.041,23.233 59.086,23.233 59.682,23.83 59.9,23.83 60.037,23.967 60.487,23.967 61.05,24.53 61.05,25.05 61.4,25.4 v1(61.5,25.4)
VPA: C80.1 C81.1 C82.1 R40.2 TP36.1 W2.2 | length 100.5
  Top Layer w1: TP36.1@26.649,80.051 R40.2@29.2,80.051 29.1,80.151 W2.2@29.1,84.16
  Bottom Layer w0.3: C82.1@98.675,30.275 C82.1@98.7,30.3
  Bottom Layer w1: W2.2@29.1,84.16 76.11,37.15 78.861,37.15 85.811,30.2 88.4,30.2 ; C80.1@88.4,31.369 88.4,30.2 ; 94.49,31.305 93.385,30.2 88.4,30.2 ; 94.685,31.3 95.398,30.588 98.387,30.588 C82.1@98.688,30.287 ; 94.71,31.331 94.713,31.328
VPA_EN: IC4.4 U4.57 | length 56.6
  Top Layer w0.15: v2(17.4,71.7) 17.4,73.556 IC4.4@17.402,73.558 ; v2(28.9,25.3) 29.022,25.3 29.276,25.046 U4.57@32.385,25.046
  Bottom Layer w0.15: v2(17.4,71.7) 19.475,69.625 19.475,34.725 v2(28.9,25.3)
pads on no net: FD1.0 FD2.0 FD3.0 IC1.1 IC1.2 IC1.10 IC1.11 IC1.12 IC1.13 IC1.14 IC1.15 IC1.16 IC1.17 IC1.18 IC1.19 IC1.20 IC1.21 IC1.22 IC1.27 IC1.28 IC3.3 IC3.4 IC3.5 IC3.6 IC3.7 IC3.8 IC3.10 IC3.13 IC3.14 IC3.15 IC3.16 IC3.17 IC3.18 J6. P1.4 P2.6 P2.7 P2.8 P2.MH1 P2.MH2 T1.6 T2.6 T3.2 T3.6 T6.6 U1. U4.1 U4.7 U4.10 U4.36 U4.62 U4.63

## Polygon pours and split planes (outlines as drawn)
GND on Ground Layer "GND_L02_P012" (solid, pour order 12): 130,43 130,90 0,90 0,0 130,0 130,11 123,4 68,4 63,9 63,29 81,43
GND on Ground Layer "GND_L02_P011" (solid, pour order 11): 64,28 81.925,42.3 130,42.3 130,12 122.6,5 68,5 64,9
GND on Top Layer " " (solid, remove dead copper, pour order 16): 130,43 130,90 0,90 0,0 130,0 130,11 123,4 68,4 63,9 63,29 81,43
GND on Top Layer "GND_L01_P015" (solid, pour order 15): 64,28.041 81.926,42.341 130,42.341 130,12.4 122.641,5.041 68,5.041 64,9.041
GND on Bottom Layer "GND_L04_P029" (solid, remove dead copper, pour order 29): 130,43 130,90 0,90 0,0 130,0 130,11 123,4 68,4 63,9 63,29 81,43
GND on Bottom Layer "GND_L04_P028" (solid, pour order 28): 64.038,28.033 81.963,42.333 130,42.333 130,12.4 122.633,5.033 68.038,5.033 64.038,9.033
3V3 on Power Layer "3V3_L03_P027" (solid, remove dead copper, pour order 27): 0,90 130,90 130,0 0,0

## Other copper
Top Layer:
  text "TOP" at 54.1,87.6 h0.8
  text "1" at 63,86.7 h0.8
Ground Layer:
  text "2" at 64.933,86.705 h0.8
Power Layer:
  text "3" at 67.5,86.7 h0.8
Bottom Layer:
  text "BOTTOM" at 59.8,87.5 h0.8
  text "4" at 71.9,86.7 h0.8

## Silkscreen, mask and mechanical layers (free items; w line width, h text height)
Top Overlay:
  circle w0.254: c62.598,61.802 r1.414
  circle w0.254: c72.598,74.802 r2.828
  circle w0.254: c52.598,74.802 r2.828
  circle w0.254: c62.598,64.802 r11.314
  circle w0.254: c1.75,72.14 r0.75
  circle w0.254: c5.75,72.14 r0.75
  circle w0.5: c3.75,72.14 r0.1
  lines w0.254: 1.5,72.14 2,72.14 ; 2.5,72.14 3,72.14 ; 3.75,72.14 5,72.14 ; 4.28,72.67 ccw(c3.75,72.14) 4.374,71.724 ; 5.5,72.14 6,72.14 ; 5.75,71.89 5.75,72.39 ; 14.6,21.6 15.3,22.3 23.3,22.3 24,21.6 ; 18.7,22.3 21.1,22.3 22.1,23.3 ; 55.598,69.802 57.598,67.802 61.598,67.802 ; 56.775,68.625 ccw(c58.598,67.802) 60.598,67.802 ; 57.499,59.703 ccw(c62.598,64.802) 69.809,64.802 ; 63.598,67.802 67.598,67.802 69.598,69.802 ; 64.598,67.802 ccw(c66.598,67.802) 68.42,68.625 ; 77.2,22.5 76.9,22.5 76.5,22.9 ; 77.3,29.2 77,29.2 76.5,28.7 ; 77.517,78.902 cw(c72.598,74.802) 78.449,72.202 ; 78.639,80.844 cw(c72.598,74.802) 80.066,70.653 ; 79.72,82.943 cw(c72.598,74.802) 81.873,69.237 ; 80.979,85.279 cw(c72.598,74.802) 83.448,66.911 ; 123.8,21.2 ccw(c123.8,21.45) 123.8,21.7 ; 124.261,20.067 ccw(c123.8,21.45) 124.261,22.833 ; 124.56,62.163 125.012,62.163 125.012,59.663 124.512,59.663 125.637,58.538 126.762,59.663 126.262,59.663 126.262,62.163 126.81,62.163 125.667,63.306 124.56,62.199 ; 124.835,19.12 ccw(c123.8,21.45) 124.855,23.771 ; 125.917,18.01 ccw(c123.8,21.45) 125.917,24.89 ; 22.1,23.3 22.1,30.3 28,30.3 28,23.3 22.1,23.3 ; 76.5,22.9 76.5,22.9 ; 76.5,22.9 76.5,28.7 ; 76.5,22.9 71.4,22.9 71.4,28.7 75.3,28.7 76.5,28.7 ; 76.5,28.7 76.5,28.7 ; 124.31,49.6 125.31,50.6 125.31,49.85 127.31,49.85 127.31,50.85 126.56,50.85 126.56,51.35 127.81,51.35 127.81,49.35 125.31,49.35 125.31,48.6 124.31,49.6
  lines w0.3: 58.098,67.802 ccw(c58.598,67.802) 59.098,67.802 ; 66.098,67.802 ccw(c66.598,67.802) 67.098,67.802
  text "6V IN" at 1.45,73.61 h0.8
  text "HF OUT" at 122.5,15.6 h0.8
  text "uC RESET" at 5.6,11 h0.8
  text "Boot mode" at 35.6,5.3 h0.8
  text "RFID UHF READER V3.0 / HEPIA 03.22 G. PASSERI / D.CARBALLO T.DIETRICH D.CRUZ" at 44.6,1.3 h0.8
Bottom Overlay:
  lines w0.254: 55.4,14.6 54.4,14.6 55.6,15.8 56.5,15.8 56.8,16.1 56.8,16.7 ; 64.6,16.7 64.6,15.3 65.3,14.6 ; 65.3,14.6 54.2,14.6 54.2,11.3 65.3,11.3 65.3,14.6
Cutout:
  lines w0.01: 0.005,0 130,0 130,90 ; 0.005,90 130.005,90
